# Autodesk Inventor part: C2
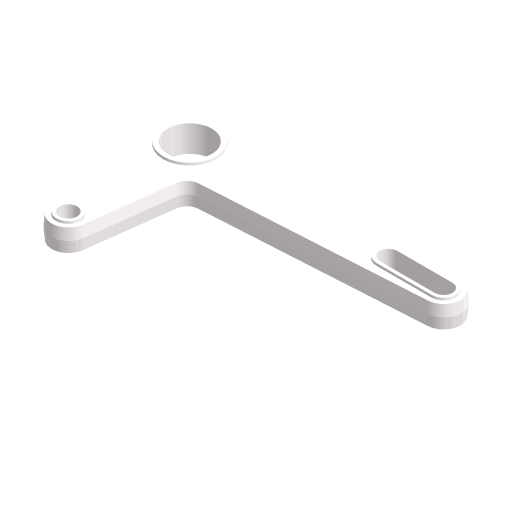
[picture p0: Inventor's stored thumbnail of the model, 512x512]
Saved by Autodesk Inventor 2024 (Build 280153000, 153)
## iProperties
Company: ATC
Shininess: 20.0
Angle Display Precision: 2
Document Length Units: 11269
Document Angle Units: 11279
Document Time Units: 11290
Document Mass Units: 11283
Document Length Units Precision: 3
Document Angle Units Precision: 2
Created: 2023-03
Part Number: C2
Material: Kurs-AJ
Document SubType Name: Modelowanie
Designer: Andrzej Jaskulski
Density: 1 g/cm^3
Appearance: Kurs-AJ
Checked By: A.J.
Engr Approved By: Andrzej Jaskulski
Mfg Approved By: Andrzej Jaskulski
Authority: A.J.
Density: 0.0
Volumn: 0.0
Area: 0.0
PropertySet Name: Model Information
Control State: 0
Master: False
Checked Out: False
Title: A.J.: Kurs R2024-MEP
Author: Andrzej Jaskulski
Revision Number: 1/24
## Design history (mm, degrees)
node "Bryła1"
node "Korpusy bryłowe"
node "Korpusy powierzchniowe"
node "Początek"
sketch "Szkic1"
  geometry: L1 (-25.035, -9.169)-(89.965, -9.169); L2 (-24.122, 5.803)-(90.452, -1.184); L3 (90.452, -17.155)-(-7.608, -23.135); L4 (-25.035, -9.169)-(-25.035, -66.201); L5 (-39.913, -11.079)-(-32.97, -65.188); L6 (-17.1, -65.188)-(-12.263, -27.489); L7 (64.965, -5.169)-(89.965, -5.169); L8 (89.965, -13.169)-(64.965, -13.169); L9 (89.965, -3.169)-(64.965, -3.169); L10 (64.965, -15.169)-(89.965, -15.169); C1 r 12.5 at (-25.035, -9.169); C2 r 6 at (-25.035, -64.169); C3 r 4 at (-25.035, -64.169); C4 r 10 at (-25.035, -9.169); A1 r 8 centre (89.965, -9.169) between (90.452, -17.155) and (90.452, -1.184); A2 r 8 centre (-25.035, -64.169) between (-32.97, -65.188) and (-17.1, -65.188); A3 r 4 centre (64.965, -9.169) between (64.965, -5.169) and (64.965, -13.169); A4 r 4 centre (89.965, -9.169) between (89.965, -13.169) and (89.965, -5.169); A5 r 113.425 centre (-25.035, -9.169) between (67.111, -75.309) and (85.385, 16.766); A6 r 5 centre (-7.304, -28.125) between (-7.608, -23.135) and (-12.263, -27.489); A7 r 15 centre (-25.035, -9.169) between (-24.122, 5.803) and (-39.913, -11.079); A8 r 6 centre (64.965, -9.169) between (64.965, -3.169) and (64.965, -15.169); A9 r 6 centre (89.965, -9.169) between (89.965, -15.169) and (89.965, -3.169)
  constraints: 20 end point, 18 point on circle, 13 centre point, 11 tangent, 6 coincident, 2 horizontal, 2 parallel, 1 concentric, 1 perpendicular, 6 other
  dimensions: "d0" = 25 diameter of C1; "d3" = 8 radius of A2; "d4" = 8 radius of A1; "d5" = 55 distance of A2.centre L1.start; "d7" = 4 radius of A3; "d8" = 4 radius of A4 (= d7); "d9" = 115 distance of L1.start L1.end; "d10" = 25 distance of L1.end A3.centre; "d11" = 12 diameter of C2; "d12" = 8 diameter of C3; "d13" = 5 radius of A6; "d14" = 30 diameter of A7; "d15" = 20 diameter of C4; "d20" = 2 distance between parallel lines of L9 L7
extrude "Wyciągnięcie proste1" new body sketch "Szkic1" stored distance "d16" = 10; taper "d17" = -5 deg
extrude "Wyciągnięcie proste2" join sketch "Szkic1" stored distance "d18" = 12; taper "d19" = -5 deg
extrude "Wyciągnięcie proste3" cut sketch "Szkic1" extent not by distance; stored distance "d21" = 16; taper "d22" = 0 deg
node "Płaszczyzna konstrukcyjna1"
node "Płaszczyzna YZ"
node "Płaszczyzna XZ"
node "Płaszczyzna XY"
node "Oś X"
node "Oś Y"
node "Oś Z"
node "Punkt środkowy"
